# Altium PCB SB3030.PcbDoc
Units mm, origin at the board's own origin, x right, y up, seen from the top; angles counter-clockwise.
Board outline 30 x 30 mm, 2 copper layers (Top Layer, Bottom Layer); 0 components, 0 nets, 4 pads, 0 vias.
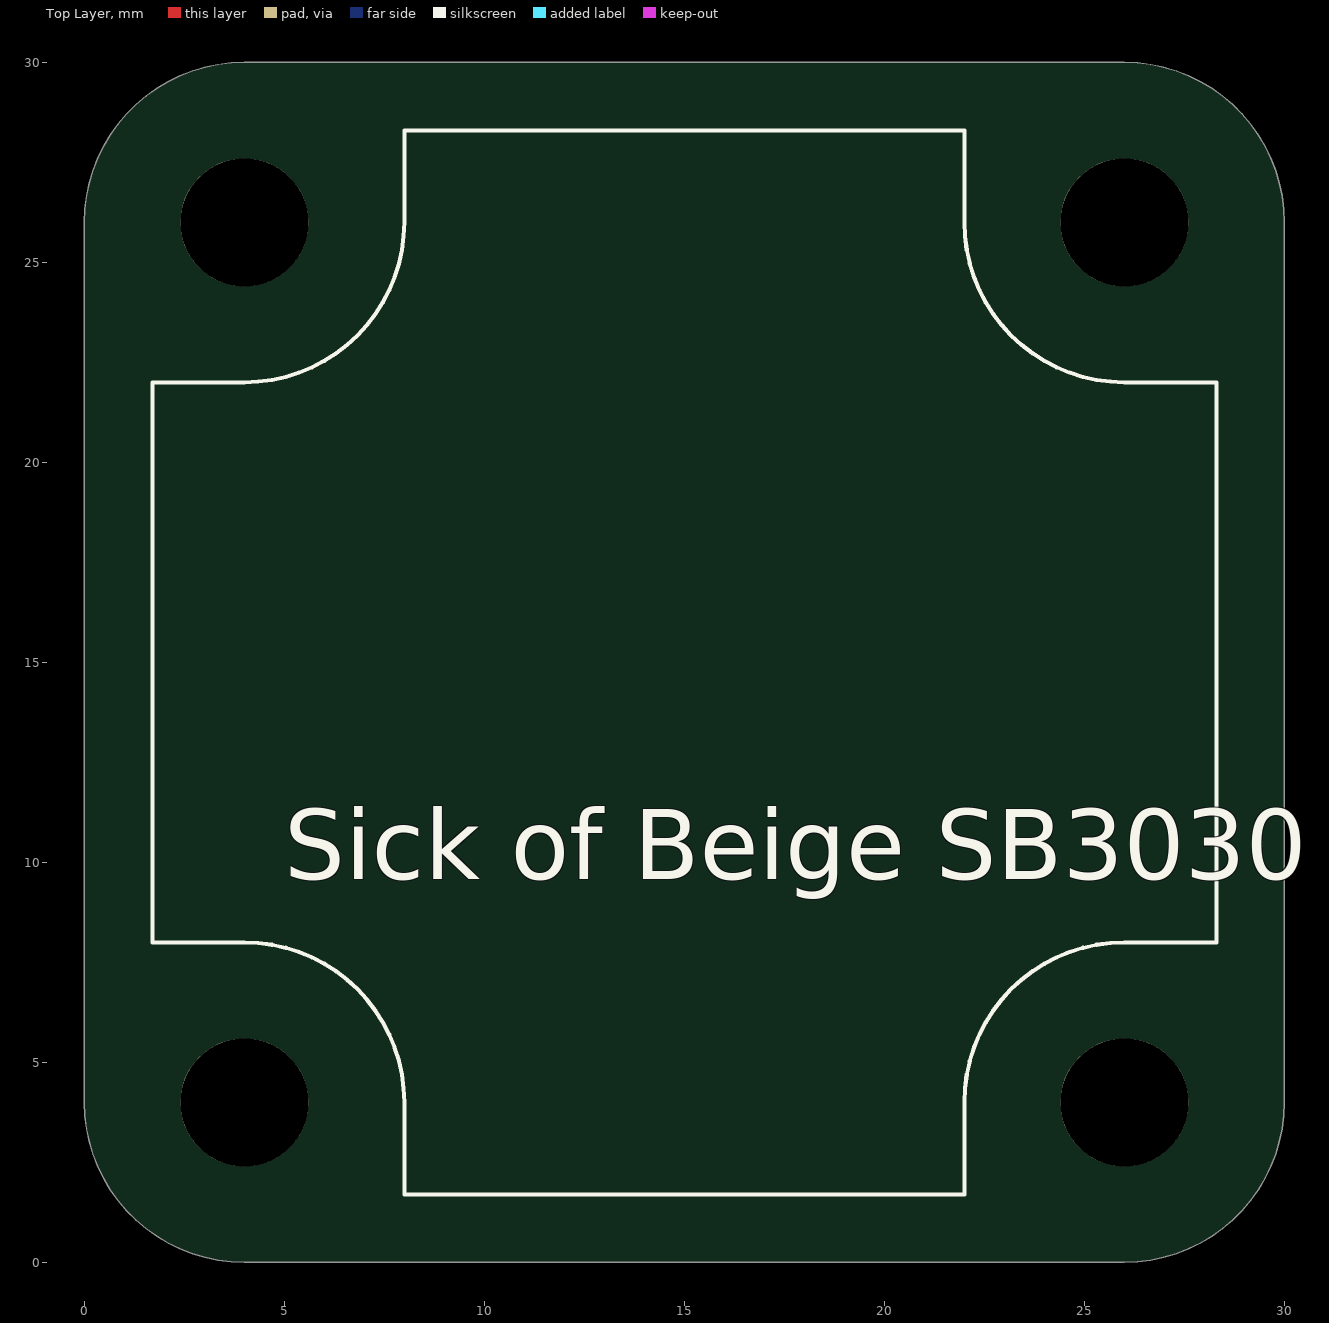
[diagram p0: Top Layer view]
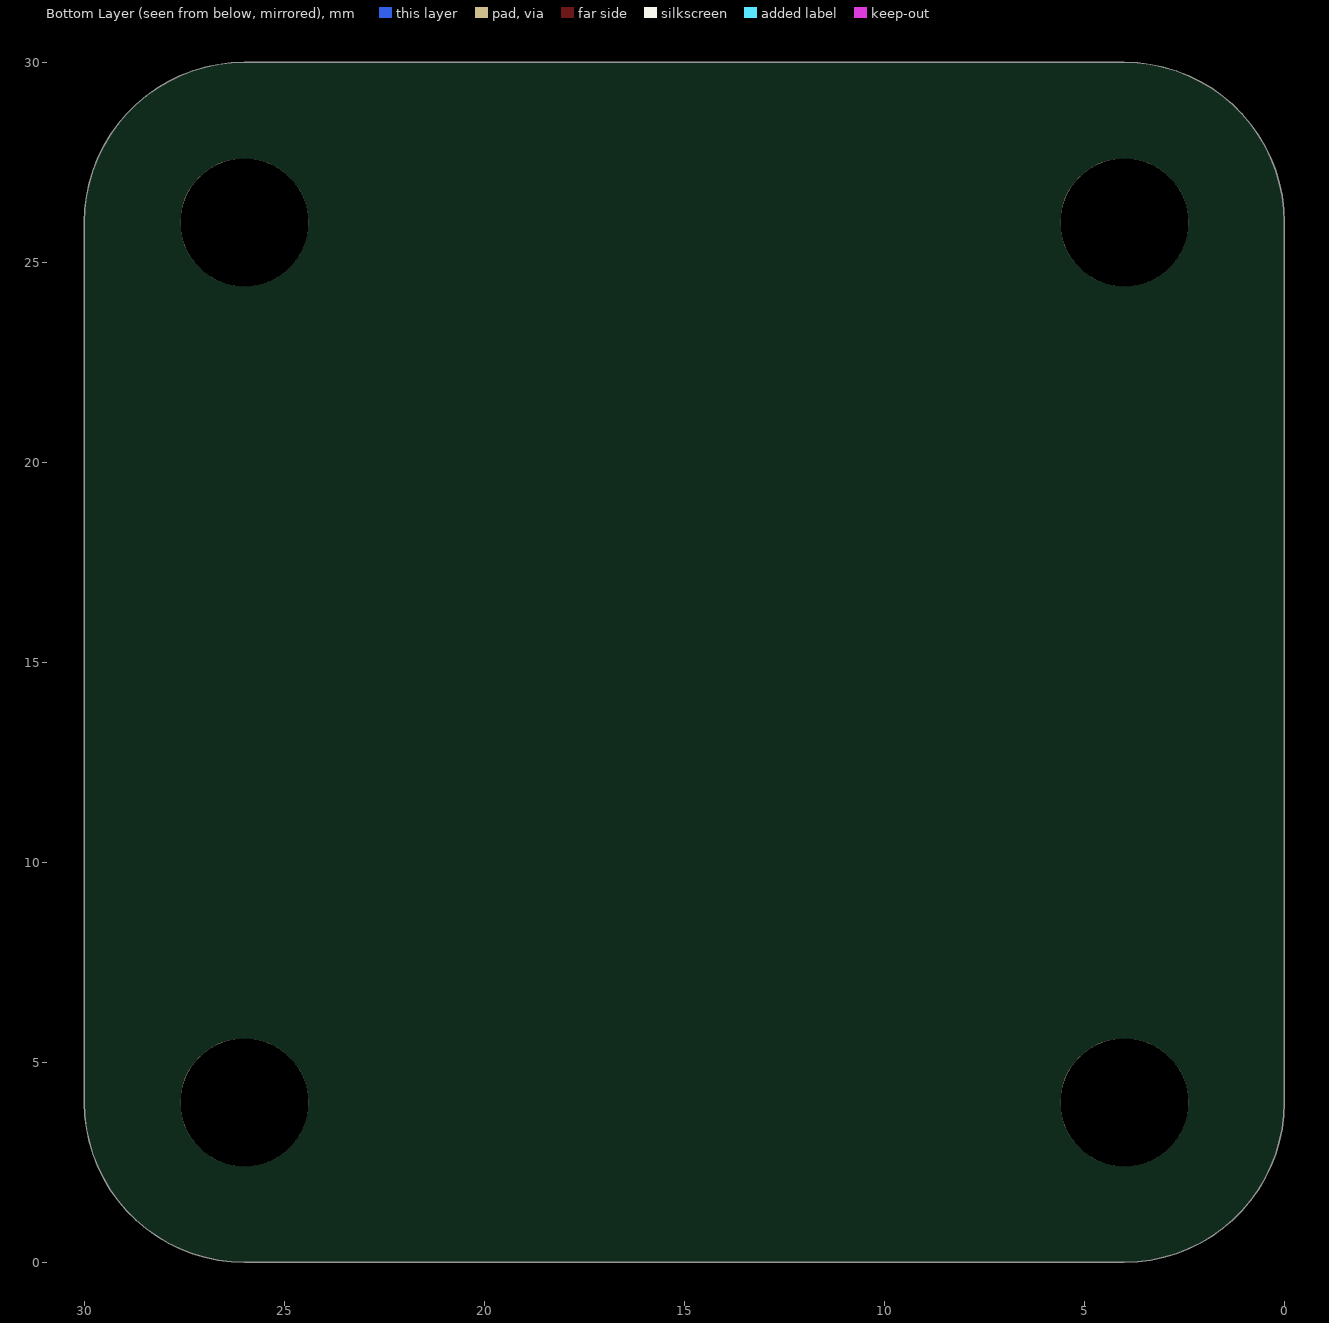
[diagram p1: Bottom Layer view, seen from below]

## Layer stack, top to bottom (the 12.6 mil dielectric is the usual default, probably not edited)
Top Layer: signal copper 0.0356
Dielectric: dielectric 0.32, FR-4, Dk 4.8
Bottom Layer: signal copper 0.0356

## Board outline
0,4 0,26 cw(c4,26) 4,30 26,30 cw(c26,26) 30,26 30,4 cw(c26,4) 26,0 4,0 cw(c4,4)

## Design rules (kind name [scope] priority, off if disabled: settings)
Clearance [All] p1: gap=0.254
PolygonConnect [All] p1: connectstyle=Relief reliefconductorwidth=0.254 reliefentries=4 polygonreliefangle="90 Angle" airgapwidth=0.254
RoutingVias [All] p1: holewidth=0.711 width=1.27 viastyle="Through Hole" minholewidth=0.711 minwidth=1.27 maxholewidth=0.711 maxwidth=1.27
SolderMaskExpansion [All] p1: expansion=0.102
Width [All] p1: maxlimit=0.254 minlimit=0.254 preferedwidth=0.254
28 further rules are at their usual default settings.

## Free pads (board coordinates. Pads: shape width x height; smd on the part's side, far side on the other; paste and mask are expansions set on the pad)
  round 3.2 hole 3.2 unplated: 0(4,4) 1(4,26) 2(26,26) 3(26,4)

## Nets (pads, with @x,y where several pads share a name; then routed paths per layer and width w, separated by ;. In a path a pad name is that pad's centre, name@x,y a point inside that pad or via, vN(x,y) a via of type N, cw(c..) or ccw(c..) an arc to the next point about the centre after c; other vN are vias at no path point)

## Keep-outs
Top Overlay:
  lines w0.102: 1.7,8 4,8 cw(c4,4) 8,4 8,1.7 22,1.7 22,4 cw(c26,4) 26,8 28.3,8 28.3,22 26,22 cw(c26,26) 22,26 22,28.3 8,28.3 8,26 cw(c4,26) 4,22 1.7,22 1.7,8

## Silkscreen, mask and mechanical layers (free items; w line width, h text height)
Top Overlay:
  text "Sick of Beige SB3030" at 5,9 h3
Mechanical 1:
  the board outline again, w0.102
Mechanical 4:
  circle w0.102: c26,26 r1.6
  circle w0.102: c4,26 r1.6
  circle w0.102: c4,4 r1.6
  circle w0.102: c26,4 r1.6
  lines w0.102: 0,15 30,15 ; 15,0 15,30

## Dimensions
26,30 to 26,0 on Mechanical 3
0,4 to 30,4 on Mechanical 3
